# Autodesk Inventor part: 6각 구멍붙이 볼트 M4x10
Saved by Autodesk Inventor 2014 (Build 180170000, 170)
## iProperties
Created: 2026-08
Part Number: 6각 구멍붙이 볼트 M4x10
Material: 일반
Document SubType Name: Modeling
Designer: dg
Density: 1 g/cm^3
Appearance: 기본값
Author: dg
Author: jhkim
Description: 6각머리 태핑 나사
Creation Date: 2026-07-31
Sending System: Autodesk Inventor 2027
Preprocessor: ST-DEVELOPER v20.1
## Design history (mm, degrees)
node "6각 구멍붙이 볼트 M4x101"
body "Solid1"
node "기준1"
